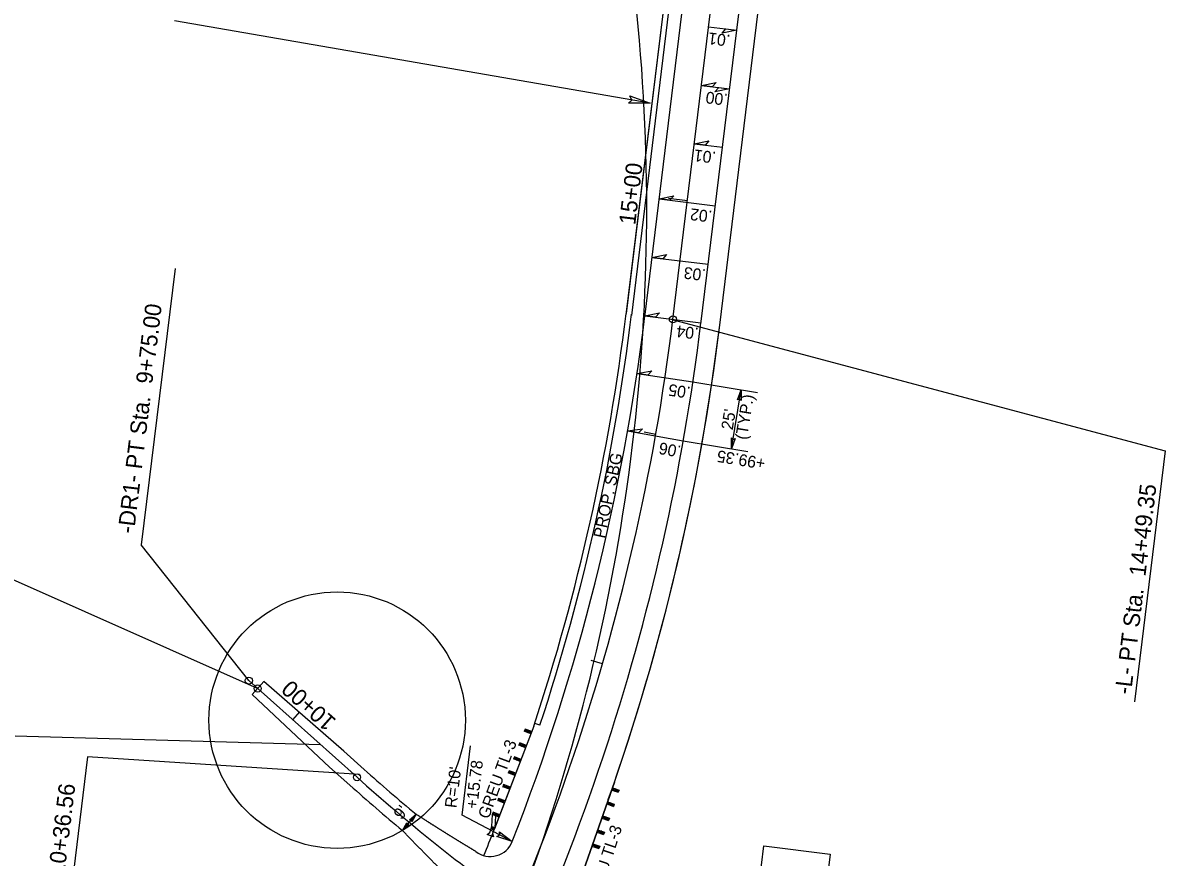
# Model space of a CAD drawing. Extents: x 472216 to 481979, y 489069 to 507339.
# Drawn here: x 480924.3 to 481409.2, y 489313.3 to 489667.2 of the extents above; entities that cross this region are included whole.
import ezdxf

# ---------------------------------------------------------------- set-up
doc = ezdxf.new("R2010")
doc.units = 0
for name, color, linetype in [('Exist Horizontal Alignment Point', 7, 'Continuous'), ('Old_Level_12', 7, 'Continuous'), ('Prop Drainage Structure Drop Inlet Grate 2 Narrow Slots and Sag Grates 840 24 CELL', 7, 'Continuous'), ('Prop Drainage Structure Drop Inlet Grate 2 Wide Slots and Sag Grates 840 22 Label', 7, 'Continuous'), ('Prop Drainage Structure Outlet Berm Ditch 850 10 CELL', 7, 'Continuous'), ('Prop Drainage Structure Pipe CSP 15in', 7, 'Continuous'), ('Prop Drainage Structure Pipe Plug CELL', 7, 'Continuous'), ('Prop Drainage Structure Pipe RCP 24in Class III Label', 7, 'Continuous'), ('Prop Drainage Structure Tops and Inverts LABEL', 7, 'Continuous'), ('Prop Earthen Structure False Sump CELL', 7, 'Continuous'), ('Prop Erosion Embankment Toe Protection CELL', 7, 'Continuous'), ('Sheet Block Revision CELL', 7, 'Continuous'), ('Sheet North Arrow Point CELL', 7, 'Continuous'), ('Sheet PE Seal Cell', 7, 'Continuous'), ('Sheet Plot Border Outside CELL', 7, 'Continuous'), ('Sheet Profile Grid Major CELL', 7, 'Continuous'), ('Sheet Profile Grid Minor CELL', 7, 'Continuous')]:
    doc.layers.add(name, color=color, linetype=linetype)

msp = doc.modelspace()

# ---------------------------------------------------------------- linework, layer by layer
at = {"layer": 'Exist Horizontal Alignment Point'}
msp.add_lwpolyline([(481231.86, 489260.64), (481238.87, 489318.02), (481266.95, 489314.59), (481259.94, 489257.21)], close=True, dxfattribs=at)
at = {"layer": 'Old_Level_12'}
for p, q in [((480988.94, 489563), (480974.62, 489445.81)), ((481198.75, 489541.64), (481409.15, 489485.69)), ((481409.15, 489485.69), (481396.14, 489379.15)), ((481023.99, 489384.85), (480870.87, 489452.76)), ((481020.26, 489388.18), (480974.62, 489445.81)), ((481050.68, 489361.01), (480921.14, 489364.55)), ((480951.77, 489355.78), (480937.46, 489238.59)), ((481067.18, 489348.29), (480951.77, 489355.78))]:
    msp.add_line(p, q, dxfattribs=at)
for centre in [(481200.24, 489541.46), (481200.24, 489541.46), (481020.26, 489388.18), (481023.99, 489384.85), (481066.18, 489347.17)]:
    msp.add_circle(centre, 1.5, dxfattribs=at)
at = {"layer": 'Prop Drainage Structure Drop Inlet Grate 2 Narrow Slots and Sag Grates 840 24 CELL'}
for p, q in [((481208.74, 489514.91), (481236.13, 489510.44)), ((481225.13, 489486.58), (481229.21, 489511.57)), ((481204.66, 489489.92), (481232.05, 489485.45))]:
    msp.add_line(p, q, dxfattribs=at)
for points in [[(481227.3, 489664.08), (481221.1, 489662.82), (481222.71, 489664.64)], [(481212.36, 489640.72), (481218.56, 489641.97), (481216.95, 489640.16)], [(481224.27, 489639.26), (481218.07, 489638), (481219.68, 489639.82)], [(481209.33, 489615.9), (481215.53, 489617.16), (481213.92, 489615.34)], [(481194.38, 489592.54), (481200.58, 489593.8), (481198.98, 489591.98)], [(481191.35, 489567.72), (481197.55, 489568.98), (481195.94, 489567.16)], [(481188.32, 489542.91), (481194.52, 489544.17), (481192.91, 489542.35)], [(481185, 489518.46), (481191.23, 489519.55), (481189.58, 489517.77)], [(481227.72, 489507.25), (481229.21, 489511.57), (481229.27, 489506.97), (481228.57, 489507.67)], [(481181.03, 489494.1), (481187.28, 489495.02), (481185.58, 489493.3)], [(481226.62, 489490.89), (481225.13, 489486.58), (481225.07, 489491.17), (481225.77, 489490.47)]]:
    msp.add_lwpolyline(points, close=True, dxfattribs=at)
at = {"layer": 'Prop Drainage Structure Drop Inlet Grate 2 Wide Slots and Sag Grates 840 22 Label'}
for p, q in [((481215.39, 489665.53), (481227.3, 489664.08)), ((481212.36, 489640.72), (481224.27, 489639.26)), ((481209.33, 489615.9), (481221.24, 489614.45)), ((481194.38, 489592.54), (481218.21, 489589.63)), ((481191.35, 489567.72), (481215.18, 489564.81)), ((481188.32, 489542.91), (481212.15, 489540)), ((481185, 489518.46), (481208.74, 489514.91)), ((481181.03, 489494.1), (481204.66, 489489.92))]:
    msp.add_line(p, q, dxfattribs=at)
at = {"layer": 'Prop Drainage Structure Outlet Berm Ditch 850 10 CELL'}
for points in [[(481181.96, 489636.22), (481190.56, 489633.16), (481181.37, 489633.12), (481182.78, 489634.5)], [(481088.45, 489329.15), (481091.23, 489331.52), (481089.41, 489328.33), (481089.21, 489329.09)], [(481088.25, 489326.97), (481085.48, 489324.6), (481087.3, 489327.79), (481087.5, 489327.03)], [(481126.63, 489324.1), (481132.07, 489319.94), (481125.51, 489322.03), (481126.83, 489322.69)]]:
    msp.add_lwpolyline(points, close=True, dxfattribs=at)
at = {"layer": 'Prop Drainage Structure Pipe Plug CELL'}
for p, q in [((481141.22, 489368.92), (481124.51, 489325.26)), ((481137.51, 489367.62), (481137.15, 489366.68)), ((481137.15, 489366.68), (481138.91, 489367.08)), ((481139.95, 489365.61), (481137.15, 489366.68)), ((481140.31, 489366.54), (481137.51, 489367.62)), ((481138.55, 489366.15), (481137.51, 489367.62)), ((481138.91, 489367.08), (481138.55, 489366.15)), ((481138.55, 489366.15), (481140.31, 489366.54)), ((481139.95, 489365.61), (481138.55, 489366.15)), ((481138.91, 489367.08), (481139.95, 489365.61)), ((481140.31, 489366.54), (481139.95, 489365.61)), ((481135.21, 489361.75), (481134.85, 489360.82)), ((481134.85, 489360.82), (481136.63, 489361.2)), ((481137.7, 489359.72), (481134.85, 489360.82)), ((481138.06, 489360.66), (481135.21, 489361.75)), ((481136.28, 489360.27), (481135.21, 489361.75)), ((481136.63, 489361.2), (481136.28, 489360.27)), ((481138.06, 489360.66), (481136.28, 489360.27)), ((481136.63, 489361.2), (481137.7, 489359.72)), ((481132.96, 489355.86), (481132.6, 489354.93)), ((481132.6, 489354.93), (481134.38, 489355.32)), ((481135.45, 489353.84), (481132.6, 489354.93)), ((481135.81, 489354.77), (481132.96, 489355.86)), ((481134.03, 489354.38), (481132.96, 489355.86)), ((481134.38, 489355.32), (481134.03, 489354.38)), ((481135.81, 489354.77), (481134.03, 489354.38)), ((481134.38, 489355.32), (481135.45, 489353.84)), ((481130.72, 489349.97), (481130.36, 489349.04)), ((481130.36, 489349.04), (481132.14, 489349.43)), ((481133.55, 489348.89), (481130.72, 489349.97)), ((481131.78, 489348.5), (481130.72, 489349.97)), ((481132.14, 489349.43), (481131.78, 489348.5)), ((481132.14, 489349.43), (481133.2, 489347.95)), ((481133.2, 489347.95), (481130.36, 489349.04)), ((481133.55, 489348.89), (481131.78, 489348.5)), ((481133.55, 489348.89), (481133.2, 489347.95)), ((481175.41, 489345.12), (481159.92, 489301.01)), ((481128.37, 489344.13), (481128.01, 489343.19)), ((481128.01, 489343.19), (481129.84, 489343.56)), ((481130.95, 489342.07), (481128.01, 489343.19)), ((481131.3, 489343), (481128.37, 489344.13)), ((481129.48, 489342.63), (481128.37, 489344.13)), ((481129.84, 489343.56), (481129.48, 489342.63)), ((481131.3, 489343), (481129.48, 489342.63)), ((481129.84, 489343.56), (481130.95, 489342.07)), ((481174.57, 489342.73), (481174.24, 489341.78)), ((481175.98, 489342.23), (481174.24, 489341.78)), ((481174.24, 489341.78), (481177.07, 489340.79)), ((481174.24, 489341.78), (481175.65, 489341.29)), ((481174.57, 489342.73), (481177.4, 489341.73)), ((481175.65, 489341.29), (481174.57, 489342.73)), ((481175.98, 489342.23), (481175.65, 489341.29)), ((481175.65, 489341.29), (481177.4, 489341.73)), ((481177.07, 489340.79), (481175.98, 489342.23)), ((481177.4, 489341.73), (481177.07, 489340.79)), ((481126.25, 489338.19), (481125.89, 489337.26)), ((481125.89, 489337.26), (481127.65, 489337.65)), ((481128.69, 489336.18), (481125.89, 489337.26)), ((481129.05, 489337.12), (481126.25, 489338.19)), ((481127.29, 489336.72), (481126.25, 489338.19)), ((481127.65, 489337.65), (481127.29, 489336.72)), ((481129.05, 489337.12), (481127.29, 489336.72)), ((481127.65, 489337.65), (481128.69, 489336.18)), ((481173.92, 489336.27), (481172.15, 489335.84)), ((481172.15, 489335.84), (481175.03, 489334.83)), ((481172.48, 489336.78), (481175.36, 489335.77)), ((481172.48, 489336.78), (481173.59, 489335.33)), ((481173.92, 489336.27), (481173.59, 489335.33)), ((481173.59, 489335.33), (481175.36, 489335.77)), ((481175.03, 489334.83), (481173.92, 489336.27)), ((481175.36, 489335.77), (481175.03, 489334.83)), ((481123.58, 489331.39), (481123.29, 489326.26)), ((481123.94, 489332.33), (481123.58, 489331.39)), ((481123.58, 489331.39), (481125.37, 489331.78)), ((481126.44, 489330.3), (481123.58, 489331.39)), ((481126.8, 489331.23), (481123.94, 489332.33)), ((481125.01, 489330.85), (481123.94, 489332.33)), ((481125.01, 489330.85), (481124.69, 489325.72)), ((481125.37, 489331.78), (481125.01, 489330.85)), ((481126.8, 489331.23), (481125.01, 489330.85)), ((481125.37, 489331.78), (481126.44, 489330.3)), ((481171.83, 489330.33), (481170.06, 489329.89)), ((481170.06, 489329.89), (481172.94, 489328.88)), ((481170.39, 489330.84), (481173.27, 489329.83)), ((481170.39, 489330.84), (481171.5, 489329.39)), ((481171.83, 489330.33), (481171.5, 489329.39)), ((481171.5, 489329.39), (481173.27, 489329.83)), ((481172.94, 489328.88), (481171.83, 489330.33)), ((481173.27, 489329.83), (481172.94, 489328.88)), ((481122.58, 489323.74), (481123.28, 489325.67)), ((481123.29, 489326.26), (481122.93, 489325.32)), ((481122.93, 489325.32), (481124.69, 489325.72)), ((481124.33, 489324.79), (481122.93, 489325.32)), ((481123.29, 489326.26), (481123.11, 489325.79)), ((481123.28, 489325.67), (481123.85, 489325.46)), ((481124.69, 489325.72), (481123.29, 489326.26)), ((481124.33, 489324.79), (481123.29, 489326.26)), ((481124.43, 489325.25), (481123.73, 489323.33)), ((481123.85, 489325.46), (481124.43, 489325.25)), ((481121.38, 489322.93), (481122.58, 489323.74)), ((481124.14, 489321.93), (481121.38, 489322.93)), ((481123.73, 489323.33), (481124.14, 489321.93)), ((481168.3, 489324.89), (481167.97, 489323.95)), ((481169.74, 489324.39), (481167.97, 489323.95)), ((481167.97, 489323.95), (481170.84, 489322.94)), ((481168.3, 489324.89), (481171.17, 489323.88)), ((481168.3, 489324.89), (481169.4, 489323.44)), ((481169.74, 489324.39), (481169.4, 489323.44)), ((481169.4, 489323.44), (481171.17, 489323.88)), ((481170.84, 489322.94), (481169.74, 489324.39)), ((481171.17, 489323.88), (481170.84, 489322.94)), ((481167.7, 489318.43), (481165.88, 489318)), ((481165.88, 489318), (481168.85, 489316.96)), ((481166.22, 489318.94), (481169.18, 489317.91)), ((481166.22, 489318.94), (481167.36, 489317.48)), ((481167.7, 489318.43), (481167.36, 489317.48)), ((481167.36, 489317.48), (481169.18, 489317.91)), ((481168.85, 489316.96), (481167.7, 489318.43)), ((481169.18, 489317.91), (481168.85, 489316.96))]:
    msp.add_line(p, q, dxfattribs=at)
at = {"layer": 'Prop Drainage Structure Pipe RCP 24in Class III Label'}
for p, q in [((481188.26, 489542.39), (481260.54, 490134.19)), ((481212.08, 489539.48), (481251.01, 489858.21)), ((481021.71, 489382.29), (481026.67, 489387.85)), ((481060.55, 489358.23), (481026.67, 489387.85)), ((481054.56, 489351.51), (481021.71, 489382.29)), ((481143.8, 489369.28), (481141.58, 489370.01)), ((481060.55, 489358.23), (481069.17, 489350.52)), ((481054.56, 489351.51), (481063.18, 489343.81))]:
    msp.add_line(p, q, dxfattribs=at)
for centre, radius, start, end in [((480277.1, 489654.21), 942, 329.97314, 353.03651), ((480277.1, 489654.21), 918, 338.64622, 353.03651), ((481609.12, 489954.98), 810.5, 228.22625, 230.28406), ((481609.12, 489954.98), 819.5, 228.22625, 230.28406), ((481122.76, 489323.58), 10, 232.3931, 338.6462)]:
    msp.add_arc(centre, radius, start, end, dxfattribs=at)
for points in [[(481116.66, 489315.66), (481116.31, 489315.87), (481115.96, 489316.08), (481115.62, 489316.28), (481115.27, 489316.49), (481114.92, 489316.7), (481114.58, 489316.91), (481114.23, 489317.12), (481113.89, 489317.33), (481113.54, 489317.54), (481113.19, 489317.74), (481112.85, 489317.95), (481112.5, 489318.16), (481112.16, 489318.37), (481111.81, 489318.58), (481111.46, 489318.79), (481111.12, 489319), (481110.77, 489319.21), (481110.43, 489319.43), (481110.08, 489319.64), (481109.74, 489319.85), (481109.39, 489320.06), (481109.05, 489320.27), (481108.7, 489320.48), (481108.36, 489320.69), (481108.01, 489320.91), (481107.67, 489321.12), (481107.32, 489321.33), (481106.98, 489321.54), (481106.63, 489321.76), (481106.29, 489321.97), (481105.95, 489322.18), (481105.6, 489322.4), (481105.26, 489322.61), (481104.91, 489322.82), (481104.57, 489323.04), (481104.23, 489323.25), (481103.88, 489323.47), (481103.54, 489323.68), (481103.2, 489323.89), (481102.85, 489324.11), (481102.51, 489324.32), (481102.17, 489324.54), (481101.82, 489324.75), (481101.48, 489324.97), (481101.14, 489325.19), (481100.79, 489325.4), (481100.45, 489325.62), (481100.11, 489325.83), (481099.76, 489326.05), (481099.42, 489326.27), (481099.08, 489326.48), (481098.74, 489326.7), (481098.39, 489326.92), (481098.05, 489327.14), (481097.71, 489327.35), (481097.37, 489327.57), (481097.03, 489327.79), (481096.68, 489328.01), (481096.34, 489328.23), (481096, 489328.45), (481095.66, 489328.66), (481095.32, 489328.88), (481094.98, 489329.1), (481094.64, 489329.32), (481094.29, 489329.54), (481093.95, 489329.76), (481093.61, 489329.98), (481093.27, 489330.2), (481092.93, 489330.42), (481092.59, 489330.64), (481092.25, 489330.86), (481091.91, 489331.08), (481091.23, 489331.52)], [(481106.89, 489302.98), (481106.6, 489303.27), (481106.3, 489303.56), (481106.01, 489303.85), (481105.71, 489304.13), (481105.42, 489304.42), (481105.12, 489304.71), (481104.83, 489305), (481104.54, 489305.29), (481104.24, 489305.58), (481103.95, 489305.86), (481103.65, 489306.15), (481103.36, 489306.44), (481103.07, 489306.73), (481102.77, 489307.02), (481102.48, 489307.31), (481102.19, 489307.6), (481101.89, 489307.89), (481101.6, 489308.18), (481101.31, 489308.47), (481101.02, 489308.76), (481100.73, 489309.05), (481100.43, 489309.34), (481100.14, 489309.63), (481099.85, 489309.92), (481099.56, 489310.21), (481099.27, 489310.5), (481098.98, 489310.79), (481098.69, 489311.08), (481098.39, 489311.37), (481098.1, 489311.66), (481097.81, 489311.95), (481097.52, 489312.25), (481097.23, 489312.54), (481096.94, 489312.83), (481096.65, 489313.12), (481096.36, 489313.41), (481096.07, 489313.7), (481095.78, 489314), (481095.49, 489314.29), (481095.21, 489314.58), (481094.92, 489314.87), (481094.63, 489315.17), (481094.34, 489315.46), (481094.05, 489315.75), (481093.76, 489316.05), (481093.48, 489316.34), (481093.19, 489316.63), (481092.9, 489316.93), (481092.61, 489317.22), (481092.32, 489317.51), (481092.04, 489317.81), (481091.75, 489318.1), (481091.46, 489318.4), (481091.18, 489318.69), (481090.89, 489318.98), (481090.6, 489319.28), (481090.32, 489319.57), (481090.03, 489319.87), (481089.75, 489320.16), (481089.46, 489320.46), (481089.17, 489320.75), (481088.89, 489321.05), (481088.6, 489321.34), (481088.32, 489321.64), (481088.03, 489321.93), (481087.75, 489322.23), (481087.46, 489322.53), (481087.18, 489322.82), (481086.9, 489323.12), (481086.61, 489323.41), (481086.33, 489323.71), (481086.04, 489324.01), (481085.48, 489324.6)]]:
    msp.add_spline(points, degree=3, dxfattribs=at)
at = {"layer": 'Prop Drainage Structure Tops and Inverts LABEL'}
for p, q in [((481226.81, 489923.96), (481180.38, 489543.87)), ((481220.09, 489539.03), (481251.99, 489800.24))]:
    msp.add_line(p, q, dxfattribs=at)
for radius, start, end in [(910, 341.72942, 353.03651), (950, 341.01317, 353.03623)]:
    msp.add_arc((480277.1, 489654.21), radius, start, end, dxfattribs=at)
at = {"layer": 'Prop Earthen Structure False Sump CELL'}
msp.add_line((481219.15, 489842.03), (481182.64, 489543.08), dxfattribs=at)
msp.add_arc((480277.1, 489654.21), 912.33, 341.80195, 353.03651, dxfattribs=at)
at = {"layer": 'Prop Erosion Embankment Toe Protection CELL'}
for p, q in [((481226.81, 489923.96), (481180.32, 489543.36)), ((481220.09, 489539.03), (481251.99, 489800.24)), ((481141.22, 489368.92), (481124.27, 489324.7)), ((481158.84, 489297.94), (481175.41, 489345.12))]:
    msp.add_line(p, q, dxfattribs=at)
for radius, start, end in [(910, 341.72942, 353.03651), (950, 340.53791, 353.03623), (909, 338.01872, 338.74634)]:
    msp.add_arc((480277.1, 489654.21), radius, start, end, dxfattribs=at)
at = {"layer": 'Sheet Block Revision CELL'}
for p, q in [((481190.56, 489633.16), (480988.75, 489668.08)), ((481110.81, 489331.08), (481114.39, 489360.45)), ((481085.48, 489324.6), (481091.23, 489331.52)), ((481132.07, 489319.94), (481110.81, 489331.08))]:
    msp.add_line(p, q, dxfattribs=at)
at = {"layer": 'Sheet North Arrow Point CELL'}
for p, q in [((481200.24, 489541.46), (481402.27, 491195.58)), ((481020.26, 489388.18), (481066.18, 489347.17))]:
    msp.add_line(p, q, dxfattribs=at)
for centre, radius, start, end in [((480354.13, 489588.27), 835, 340.49976, 6.54581), ((480277.1, 489654.21), 930, 328.94039, 353.03651), ((481609.12, 489954.98), 815, 228.22625, 234.34001)]:
    msp.add_arc(centre, radius, start, end, dxfattribs=at)
at = {"layer": 'Sheet PE Seal Cell'}
for p, q in [((481192.95, 489492.65), (481188.03, 489493.52)), ((481170.33, 489395.29), (481165.52, 489396.68))]:
    msp.add_line(p, q, dxfattribs=at)
at = {"layer": 'Sheet Plot Border Outside CELL'}
msp.add_circle((481057.74, 489371.41), 54.41, dxfattribs=at)
at = {"layer": 'Sheet Profile Grid Minor CELL'}
for p, q in [((481206.38, 489591.73), (481198.43, 489592.7)), ((481038.9, 489371.51), (481041.9, 489374.88))]:
    msp.add_line(p, q, dxfattribs=at)

# ---------------------------------------------------------------- texts
at = {"layer": 'Old_Level_12'}
for s, p in [('-DR1- PT Sta.  9+75.00', (480971.49, 489450.29)), ('-L- PT Sta.  14+49.35', (481394.63, 489382.08)), ('-DR1- PC Sta.  10+36.56', (480934.02, 489240.55))]:
    msp.add_text(s, height=7, rotation=83.0365, dxfattribs=at).set_placement(p)
at = {"layer": 'Prop Drainage Structure Drop Inlet Grate 2 Narrow Slots and Sag Grates 840 24 CELL'}
for s, rotation, p in [('.01', 173.0359, (481224.81, 489662.08)), ('.00', 173.0359, (481223.74, 489637.02)), ('.01', 173.0359, (481218.74, 489612.45)), ('.02', 173.0359, (481217.13, 489587.45)), ('.03', 173.0359, (481214.43, 489562.6)), ('.04', 173.0359, (481211.34, 489537.79)), ('.05', 171.4962, (481207.95, 489512.71)), ('(TYP.)', 80.7261, (481231.56, 489490.14)), ("25'", 80.7261, (481225.61, 489494.32)), ('.06', 169.956, (481203.97, 489487.71)), ('+99.35', 170.7261, (481239.79, 489482.63))]:
    msp.add_text(s, height=5, rotation=rotation, dxfattribs=at).set_placement(p)
at = {"layer": 'Prop Drainage Structure Pipe CSP 15in'}
for s, rotation, p in [('PROP. SBG', 78.0321, (481171.3, 489448.28)), ('+15.78', 83.0365, (481117.16, 489333.62)), ("R=10'", 83.0365, (481108.32, 489333.95)), ("9'", 50.2841, (481085.05, 489328.81))]:
    msp.add_text(s, height=5, rotation=rotation, dxfattribs=at).set_placement(p)
at = {"layer": 'Prop Drainage Structure Pipe Plug CELL'}
for rotation, p in [(69.8569, (481122.03, 489329.16)), (71.9446, (481167.93, 489292.63))]:
    msp.add_text('GREU TL-3', height=5, rotation=rotation, dxfattribs=at).set_placement(p)
at = {"layer": 'Sheet Profile Grid Major CELL'}
for s, rotation, p in [('15+00', 83.0365, (481184.25, 489581.32)), ('10+00', 138.2262, (481057.74, 489371.41))]:
    msp.add_text(s, height=7, rotation=rotation, dxfattribs=at).set_placement(p)

doc.saveas('drawing.dxf')
